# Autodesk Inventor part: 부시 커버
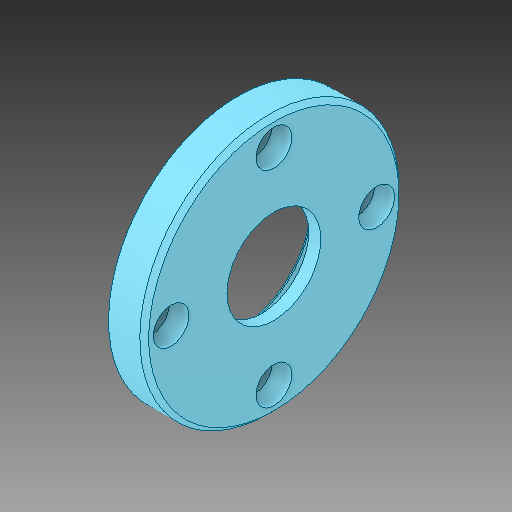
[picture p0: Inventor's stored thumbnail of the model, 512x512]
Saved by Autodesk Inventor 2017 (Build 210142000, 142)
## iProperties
Created: 2024-08
Part Number: 부시 커버
Material: 일반
Document SubType Name: Modeling
Designer: MRC
Density: 1 g/cm^3
Appearance: 기본값
Author: jhkim
Sending System: Autodesk Inventor 2025
Preprocessor: ST-DEVELOPER v20
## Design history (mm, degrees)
feature "솔리드1"
node "솔리드2"
